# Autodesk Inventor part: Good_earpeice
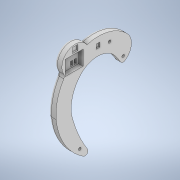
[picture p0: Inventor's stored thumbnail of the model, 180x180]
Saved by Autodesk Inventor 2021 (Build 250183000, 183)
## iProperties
Created: 2021-02
Part Number: Good_earpeice
Material: Generic
Document SubType Name: Modeling
Designer: callu
Density: 1 g/cm^3
Appearance: Default
Author: callu
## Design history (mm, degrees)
sketch "Sketch2" dims "d26" = 0, "d27" = 0
  geometry: L1 (-25.305, 31.037)-(-25.305, 31.017); L2 (-14.045, -3.328)-(-14.045, -3.328); L3 (21.541, 20.68)-(1.041, 20.68); L4 (1.041, 20.68)-(1.041, -6.12); L5 (1.041, -6.12)-(21.541, -6.12); L6 (21.541, -6.12)-(21.541, 20.68); A1 r 27.085 centre (-15.75, 12.927) between (3.057, -6.564) and (10.201, 20.68); A2 r 34.213 centre (-20.037, 7.225) between (-0.462, 35.285) and (-23.063, 41.304); A3 r 15.394 centre (-15.456, 13.46) between (-3.961, 3.221) and (-5.132, 24.879); A4 r 24.822 centre (-21.779, 6.467) between (-5.132, 24.879) and (-25.305, 31.037); A5 r 9.689 centre (-3.671, 0.409) between (-12.797, -2.847) and (3.057, -6.564); A6 r 175.968 centre (-86.315, 157.028) between (-12.797, -2.847) and (-12.017, -2.486); A7 r 37.952 centre (-29.739, 31.074) between (-12.017, -2.486) and (-3.961, 3.221); A8 r 84.854 centre (-5.465, -51.465) between (-25.305, 31.037) and (-57.408, 15.633); A9 r 40.798 centre (-19.454, 0.666) between (-23.063, 41.304) and (-57.408, 15.633); A10 r 9.074 centre (5.493, 28.437) between (10.201, 20.68) and (-0.462, 35.285); 5 further points
  constraints: 21 point on circle, 12 end point, 10 centre point, 3 tangent, 2 parallel, 1 horizontal, 1 perpendicular, 12 other
  dimensions: "d77" = 20.5 distance of L5.end L4.end; "d78" = 26.8 distance of L4.end L3.end
extrude "Extrusion3" new body sketch "Sketch2" distance "d28" = 5; taper "d29" = 0 deg
fillet "Fillet4" dims "d41" = 2
sketch "Sketch4"
  geometry: L1 (-35.285, 9.005)-(-23.285, 9.005); L2 (-23.285, 9.005)-(-23.285, -0.995); L3 (-23.285, -0.995)-(-35.285, -0.995); L4 (-35.285, -0.995)-(-35.285, 9.005); L5 (-30.285, 13.505)-(-26.785, 13.505); L6 (-26.785, 13.505)-(-26.785, 10.005); L7 (-26.785, 10.005)-(-30.285, 10.005); L8 (-30.285, 10.005)-(-30.285, 13.505); 1 further point
  constraints: 16 end point, 4 parallel, 2 horizontal, 2 perpendicular
  dimensions: "d42" = 12 distance of L2.end L3.end; "d43" = 10 distance of L1.end L2.end; "d44" = 3.5 distance of L6.end L7.end; "d45" = 3.5 distance of L5.end L6.end; "d46" = 1 distance between parallel lines of L1 L7; "d47" = 3.5 distance between parallel lines of L2 L6
fillet "Fillet5" dims "d48" = 2
extrude "Extrusion4" cut sketch "Sketch4" distance "d49" = 3; taper "d50" = 0 deg
extrude "Extrusion5" cut sketch "Sketch4" distance "d51" = 1; taper "d52" = 0 deg
sketch "Sketch5"
  geometry: L1 (-24.785, 0.005)-(-26.285, 0.005); L2 (-26.285, 0.005)-(-26.285, 3.005); L3 (-26.285, 3.005)-(-24.785, 3.005); L4 (-24.785, 3.005)-(-24.785, 0.005); L5 (-23.285, 9.005)-(-23.285, -0.995) reference; L6 (-23.285, -0.995)-(-35.285, -0.995) reference; L7 (-27.285, 0.005)-(-28.785, 0.005); L8 (-28.785, 0.005)-(-28.785, 3.005); L9 (-28.785, 3.005)-(-27.285, 3.005); L10 (-27.285, 3.005)-(-27.285, 0.005); 1 further point
  constraints: 16 end point, 4 parallel, 2 horizontal, 2 perpendicular
  dimensions: "d53" = 1.5 distance of L2.end L3.end; "d54" = 3 distance of L1.end L2.end; "d55" = 1.5 distance between parallel lines of L5 L4; "d56" = 1 distance between parallel lines of L6 L1; "d57" = 1.5 distance of L8.end L9.end; "d58" = 1 distance between parallel lines of L2 L10; "d59" = 1 distance between parallel lines of L6 L7
extrude "Extrusion6" cut sketch "Sketch5" distance "d60" = 2; taper "d61" = 0 deg
fillet "Fillet6" dims "d62" = 2.5
fillet "Fillet7" dims "d63" = 0.5
sketch "Sketch6"
  geometry: L1 (-14.5, 7.5)-(-12, 7.5); L2 (-12, 7.5)-(-12, 4.5); L3 (-12, 4.5)-(-14.5, 4.5); L4 (-14.5, 4.5)-(-14.5, 7.5); 5 further points
  constraints: 8 end point, 2 parallel, 1 horizontal, 1 perpendicular
  dimensions: "d64" = 3.75 horizontal distance of point (3.75, -8.5) point (0, 0); "d65" = 8.5 vertical distance of point (0, 0) point (3.75, -8.5); "d68" = 25.5 horizontal distance of point (0, 0) point (-25.5, -48); "d69" = 48 vertical distance of point (-25.5, -48) point (0, 0); "d79" = 2.5 distance of L2.end L3.end; "d80" = 3 distance of L1.end L2.end; "d81" = 12 distance from line of L2 point (0, 0); "d82" = 4.5 distance from line of point (0, 0) L3; "d83" = 5.5 horizontal distance of point (0, 0) point (-5.5, 4.5); "d84" = 4.5 vertical distance of point (0, 0) point (-5.5, 4.5)
hole "Hole1" sketch "Sketch6" diameter "d70" = 1.778; stored, may be unused: countersink angle "d74" = 82 deg, drill point angle "d76" = 118 deg; dims "d71" = 6, "d72" = 3.023, "d73" = 2, "d75" = 3
extrude "Extrusion7" cut sketch "Sketch6" distance "d85" = 0.95; taper "d86" = 0 deg
body "Solid3"
